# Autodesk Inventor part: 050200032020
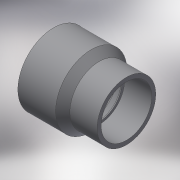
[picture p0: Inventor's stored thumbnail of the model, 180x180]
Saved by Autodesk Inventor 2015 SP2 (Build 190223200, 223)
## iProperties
Created: 2017-10
Part Number: 050200032020
Material: Generic
Description: PLASSON REDUCING SOCKET M.F.32(25)20 CEMENTED
Document SubType Name: Modeling
Designer: KIM
Density: 1 g/cm^3
Appearance: Default
Author: KIM
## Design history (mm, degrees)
derived "050200.ipt"
feature "Solid1::050200.ipt"
tag "TaggingFeature1"
body "Solid1"
other parameters: "d0" = 45, "d1" = 22, "d2" = 19, "d3" = 19, "d5" = 25, "d6" = 25, "d7" = 32, "d8" = 18, "d9" = 45 deg, "d12" = 0.25, "d_" = 25, "L_" = 22, "l_" = 19, "l_1" = 19, "E_" = 25, "H_" = 45, "D_" = 32, "d11" = 7.1883
